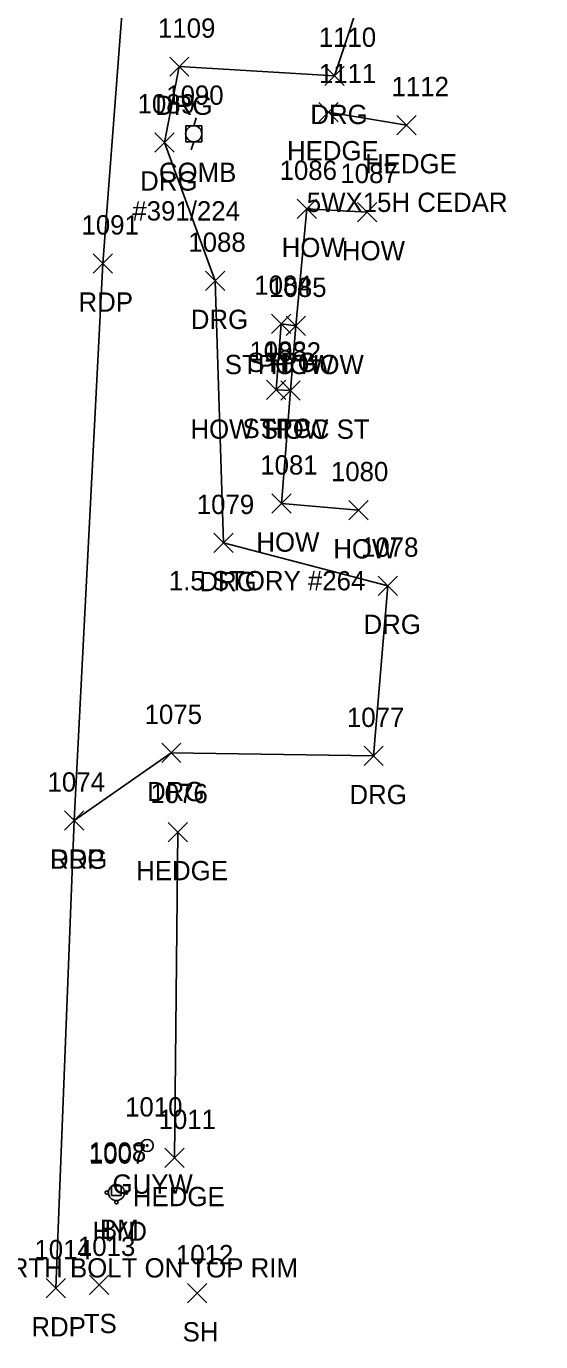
# Model space of a CAD drawing. Extents: x 1653908 to 1654393, y 539913 to 544256.
# Drawn here: x 1654023.6 to 1654076.9, y 541016.2 to 541152.6 of the extents above; entities that cross this region are included whole.
import ezdxf

# ---------------------------------------------------------------- set-up
doc = ezdxf.new("R2010")
doc.units = 0
for name, color, linetype in [('C_A', 7, 'Continuous'), ('C_C', 7, 'Continuous'), ('C_I', 7, 'Continuous'), ('CPBM', 7, 'Continuous'), ('L_A', 7, 'Continuous'), ('L_C', 7, 'Continuous'), ('L_I', 7, 'Continuous'), ('L_TIC', 7, 'Continuous'), ('LAHR', 7, 'Continuous'), ('LBC', 7, 'Continuous'), ('LBF', 7, 'Continuous'), ('P_A', 7, 'Continuous'), ('P_I', 7, 'Continuous'), ('P_TIC', 7, 'Continuous'), ('PET', 7, 'Continuous'), ('R_A', 7, 'Continuous'), ('R_I', 7, 'Continuous'), ('R_TIC', 7, 'Continuous'), ('RDG', 7, 'Continuous'), ('U_A', 7, 'Continuous'), ('U_C', 7, 'Continuous'), ('U_I', 7, 'Continuous'), ('UP', 7, 'Continuous'), ('UPGW', 7, 'Continuous'), ('UWFH', 7, 'Continuous')]:
    doc.layers.add(name, color=color, linetype=linetype)

msp = doc.modelspace()

# ---------------------------------------------------------------- linework, layer by layer
at = {"layer": 'CPBM'}
for p, q in [((1654032.4, 541031.38), (1654032.4, 541032.38)), ((1654032.4, 541032.38), (1654033.4, 541032.38)), ((1654032.9, 541031.88), (1654032.9, 541031.88)), ((1654032.9, 541031.88), (1654032.9, 541031.88)), ((1654033.4, 541032.38), (1654033.4, 541031.38)), ((1654033.4, 541031.38), (1654032.4, 541031.38))]:
    msp.add_line(p, q, dxfattribs=at)
at = {"layer": 'L_TIC'}
for points in [[(1654053.89, 541142.67), (1654055.89, 541144.67)], [(1654055.89, 541142.67), (1654053.89, 541144.67)], [(1654061.98, 541141.32), (1654063.98, 541143.32)], [(1654063.98, 541141.32), (1654061.98, 541143.32)], [(1654051.65, 541132.64), (1654053.65, 541134.64)], [(1654053.65, 541132.64), (1654051.65, 541134.64)], [(1654057.89, 541132.31), (1654059.89, 541134.31)], [(1654059.89, 541132.31), (1654057.89, 541134.31)], [(1654048.97, 541120.73), (1654050.97, 541122.73)], [(1654050.97, 541120.73), (1654048.97, 541122.73)], [(1654050.51, 541120.51), (1654052.51, 541122.51)], [(1654052.51, 541120.51), (1654050.51, 541122.51)], [(1654050.51, 541120.51), (1654052.51, 541122.51)], [(1654052.51, 541120.51), (1654050.51, 541122.51)], [(1654048.47, 541113.89), (1654050.47, 541115.89)], [(1654050.47, 541113.89), (1654048.47, 541115.89)], [(1654049.95, 541113.81), (1654051.95, 541115.81)], [(1654051.95, 541113.81), (1654049.95, 541115.81)], [(1654049.95, 541113.81), (1654051.95, 541115.81)], [(1654051.95, 541113.81), (1654049.95, 541115.81)], [(1654049.02, 541102.1), (1654051.02, 541104.1)], [(1654051.02, 541102.1), (1654049.02, 541104.1)], [(1654057, 541101.41), (1654059, 541103.41)], [(1654059, 541101.41), (1654057, 541103.41)], [(1654038.26, 541068.05), (1654040.26, 541070.05)], [(1654040.26, 541068.05), (1654038.26, 541070.05)], [(1654037.92, 541034.27), (1654039.92, 541036.27)], [(1654039.92, 541034.27), (1654037.92, 541036.27)], [(1654030.12, 541021.11), (1654032.12, 541023.11)], [(1654032.12, 541021.11), (1654030.12, 541023.11)], [(1654040.28, 541020.25), (1654042.28, 541022.25)], [(1654042.28, 541020.25), (1654040.28, 541022.25)]]:
    msp.add_lwpolyline(points, dxfattribs=at)
at = {"layer": 'LAHR'}
for points in [[(1654054.89, 541143.67), (1654062.98, 541142.32)], [(1654038.92, 541035.27), (1654039.26, 541069.05)]]:
    msp.add_lwpolyline(points, dxfattribs=at)
at = {"layer": 'LBC'}
msp.add_lwpolyline([(1654058, 541102.41), (1654050.02, 541103.1), (1654050.95, 541114.81), (1654051.51, 541121.51), (1654052.65, 541133.64), (1654058.89, 541133.31)], dxfattribs=at)
at = {"layer": 'LBF'}
msp.add_lwpolyline([(1654050.95, 541114.81), (1654049.47, 541114.89), (1654049.97, 541121.73), (1654051.51, 541121.51)], dxfattribs=at)
at = {"layer": 'P_TIC'}
for points in [[(1654030.49, 541126.98), (1654032.49, 541128.98)], [(1654032.49, 541126.98), (1654030.49, 541128.98)], [(1654027.54, 541069.24), (1654029.54, 541071.24)], [(1654029.54, 541069.24), (1654027.54, 541071.24)], [(1654025.62, 541020.77), (1654027.62, 541022.77)], [(1654027.62, 541020.77), (1654025.62, 541022.77)]]:
    msp.add_lwpolyline(points, dxfattribs=at)
at = {"layer": 'PET'}
msp.add_lwpolyline([(1654026.62, 541021.77), (1654028.54, 541070.24), (1654031.49, 541127.98), (1654037.66, 541208.54), (1654042.53, 541248.32), (1654044.37, 541265.21), (1654043.73, 541271.44), (1654047, 541298.33), (1654052.52, 541346.47), (1654054.45, 541365.83), (1654058.25, 541433.29), (1654064.32, 541497.28)], dxfattribs=at)
at = {"layer": 'R_TIC'}
for points in [[(1654038.43, 541147.38), (1654040.43, 541149.38)], [(1654040.43, 541147.38), (1654038.43, 541149.38)], [(1654054.52, 541146.43), (1654056.52, 541148.43)], [(1654056.52, 541146.43), (1654054.52, 541148.43)], [(1654036.88, 541139.53), (1654038.88, 541141.53)], [(1654038.88, 541139.53), (1654036.88, 541141.53)], [(1654042.13, 541125.19), (1654044.13, 541127.19)], [(1654044.13, 541125.19), (1654042.13, 541127.19)], [(1654043.02, 541098.01), (1654045.02, 541100.01)], [(1654045.02, 541098.01), (1654043.02, 541100.01)], [(1654060.03, 541093.58), (1654062.03, 541095.58)], [(1654062.03, 541093.58), (1654060.03, 541095.58)], [(1654037.6, 541076.25), (1654039.6, 541078.25)], [(1654039.6, 541076.25), (1654037.6, 541078.25)], [(1654058.57, 541075.94), (1654060.57, 541077.94)], [(1654060.57, 541075.94), (1654058.57, 541077.94)], [(1654027.54, 541069.24), (1654029.54, 541071.24)], [(1654029.54, 541069.24), (1654027.54, 541071.24)]]:
    msp.add_lwpolyline(points, dxfattribs=at)
at = {"layer": 'RDG'}
msp.add_lwpolyline([(1654028.54, 541070.24), (1654038.6, 541077.25), (1654059.57, 541076.94), (1654061.03, 541094.58), (1654044.02, 541099.01), (1654043.13, 541126.19), (1654037.88, 541140.53), (1654039.43, 541148.38), (1654055.52, 541147.43), (1654059.02, 541158.08), (1654052.9, 541167.53), (1654052.51, 541181.31), (1654043.29, 541183.51), (1654044.31, 541207.87), (1654064.52, 541208.31), (1654065.22, 541218.28), (1654063.37, 541224.33), (1654050.59, 541229.36), (1654050.9, 541232.24), (1654056.12, 541263.02), (1654051.65, 541275.04), (1654060.14, 541280.34), (1654076.88, 541278.82)], dxfattribs=at)
at = {"layer": 'UP'}
for p, q in [((1654040.09, 541140.59), (1654040.09, 541142.26)), ((1654040.09, 541142.26), (1654041.76, 541142.26)), ((1654041.17, 541143.09), (1654040.92, 541142.26)), ((1654041.76, 541142.26), (1654041.76, 541140.59)), ((1654041.76, 541140.59), (1654040.09, 541140.59)), ((1654040.67, 541139.76), (1654040.92, 541140.59)), ((1654040.92, 541141.43), (1654040.92, 541141.43))]:
    msp.add_line(p, q, dxfattribs=at)
msp.add_circle((1654040.92, 541141.43), 0.833, dxfattribs=at)
at = {"layer": 'UPGW'}
for radius in [0.625, 0.0833]:
    msp.add_circle((1654036.1, 541036.56), radius, dxfattribs=at)
at = {"layer": 'UWFH'}
msp.add_line((1654032.91, 541031.68), (1654032.91, 541031.68), dxfattribs=at)
for centre, radius in [((1654031.91, 541031.68), 0.167), ((1654032.91, 541031.68), 0.833), ((1654033.91, 541031.68), 0.167), ((1654032.91, 541030.68), 0.167)]:
    msp.add_circle(centre, radius, dxfattribs=at)

# ---------------------------------------------------------------- texts
at = {"layer": 'C_A'}
msp.add_text('BM', height=2, dxfattribs=at).set_placement((1654031.21, 541026.88))
at = {"layer": 'C_C'}
msp.add_text('TOP OF NORTH BOLT ON TOP RIM', height=2, dxfattribs=at).set_placement((1654007.15, 541022.88))
at = {"layer": 'C_I'}
msp.add_text('1008', height=2, dxfattribs=at).set_placement((1654030.05, 541034.88))
at = {"layer": 'L_A'}
for s, p in [('HEDGE', (1654050.59, 541138.67)), ('HEDGE', (1654058.68, 541137.32)), ('HOW', (1654050.04, 541128.64)), ('HOW', (1654056.28, 541128.31)), ('STPC', (1654046.48, 541116.73)), ('STPC HOW', (1654044.14, 541116.51)), ('HOW', (1654048.9, 541116.51)), ('HOW STPC ST', (1654040.58, 541109.81)), ('STPC', (1654045.98, 541109.89)), ('HOW', (1654048.33, 541109.81)), ('HOW', (1654047.41, 541098.1)), ('HOW', (1654055.39, 541097.41)), ('HEDGE', (1654034.96, 541064.05)), ('HEDGE', (1654034.62, 541030.27)), ('TS', (1654029.53, 541017.11)), ('SH', (1654039.77, 541016.25))]:
    msp.add_text(s, height=2, dxfattribs=at).set_placement(p)
at = {"layer": 'L_C'}
for s, p in [('5WX15H CEDAR', (1654052.64, 541133.32)), ('1.5 STORY #264', (1654038.34, 541094.1))]:
    msp.add_text(s, height=2, dxfattribs=at).set_placement(p)
at = {"layer": 'L_I'}
for s, p in [('1111', (1654053.9, 541146.67)), ('1112', (1654061.42, 541145.32)), ('1086', (1654049.82, 541136.64)), ('1087', (1654056.12, 541136.31)), ('1084', (1654047.2, 541124.73)), ('1085', (1654048.74, 541124.51)), ('1085', (1654048.74, 541124.51)), ('1083', (1654046.69, 541117.89)), ('1082', (1654048.17, 541117.81)), ('1082', (1654048.17, 541117.81)), ('1081', (1654047.82, 541106.1)), ('1080', (1654055.14, 541105.41)), ('1076', (1654036.43, 541072.05)), ('1011', (1654037.28, 541038.27)), ('1013', (1654028.92, 541025.11)), ('1012', (1654039.08, 541024.25))]:
    msp.add_text(s, height=2, dxfattribs=at).set_placement(p)
at = {"layer": 'P_A'}
for p in [(1654028.98, 541122.98), (1654026.03, 541065.24), (1654024.1, 541016.77)]:
    msp.add_text('RDP', height=2, dxfattribs=at).set_placement(p)
at = {"layer": 'P_I'}
for s, p in [('1091', (1654029.29, 541130.98)), ('1074', (1654025.77, 541073.24)), ('1014', (1654024.41, 541024.77))]:
    msp.add_text(s, height=2, dxfattribs=at).set_placement(p)
at = {"layer": 'R_A'}
for p in [(1654036.92, 541143.38), (1654053.01, 541142.43), (1654035.37, 541135.53), (1654040.62, 541121.19), (1654041.51, 541094.01), (1654058.52, 541089.58), (1654036.09, 541072.25), (1654057.06, 541071.94), (1654026.03, 541065.24)]:
    msp.add_text('DRG', height=2, dxfattribs=at).set_placement(p)
at = {"layer": 'R_I'}
for s, p in [('1109', (1654037.22, 541151.38)), ('1110', (1654053.88, 541150.43)), ('1089', (1654035.1, 541143.53)), ('1088', (1654040.36, 541129.19)), ('1079', (1654041.24, 541102.01)), ('1078', (1654058.26, 541097.58)), ('1075', (1654035.83, 541080.25)), ('1077', (1654056.8, 541079.94)), ('1074', (1654025.77, 541073.24))]:
    msp.add_text(s, height=2, dxfattribs=at).set_placement(p)
at = {"layer": 'U_A'}
for s, p in [('COMB', (1654037.31, 541136.43)), ('GUYW', (1654032.5, 541031.56)), ('HYD', (1654030.43, 541026.68))]:
    msp.add_text(s, height=2, dxfattribs=at).set_placement(p)
at = {"layer": 'U_C'}
msp.add_text('#391/224', height=2, dxfattribs=at).set_placement((1654034.56, 541132.43))
at = {"layer": 'U_I'}
for s, p in [('1090', (1654038.07, 541144.43)), ('1010', (1654033.81, 541039.56)), ('1007', (1654030.06, 541034.68))]:
    msp.add_text(s, height=2, dxfattribs=at).set_placement(p)

doc.saveas('drawing.dxf')
